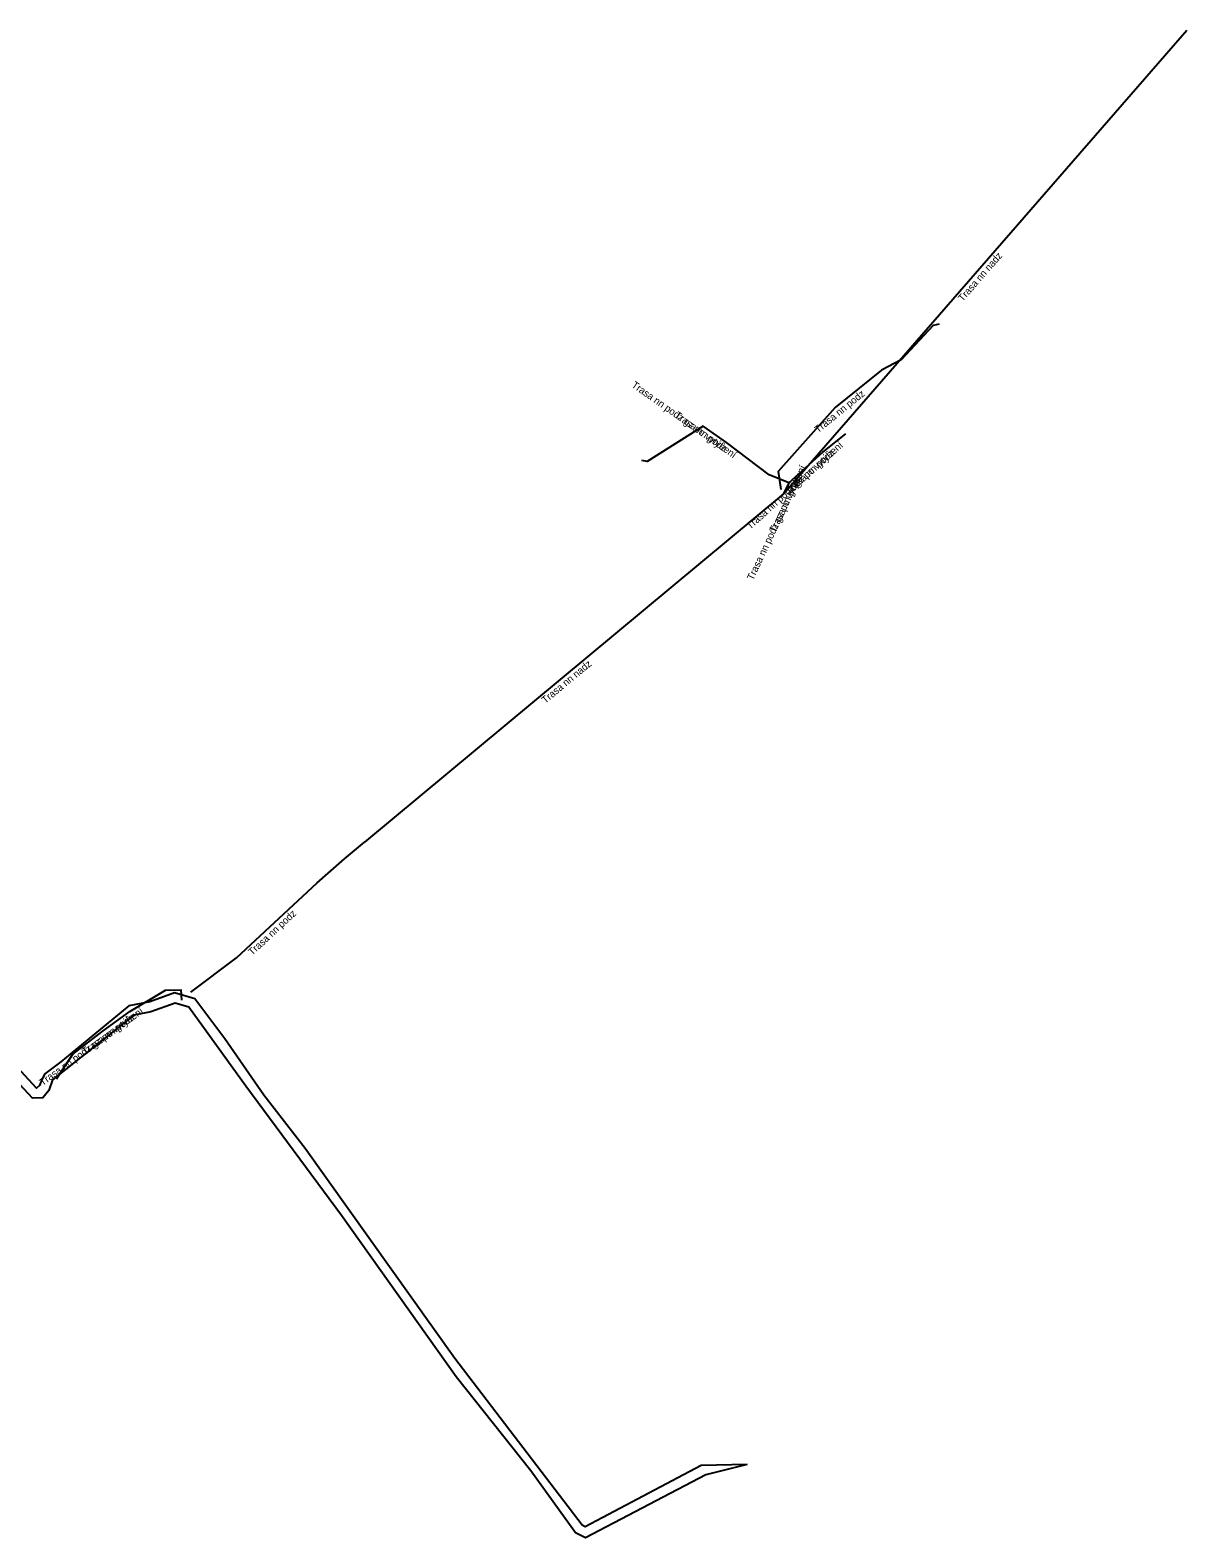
# Model space of a CAD drawing. Extents: x -703240 to -702678, y -1007635 to -1007322.
# Drawn here: x -702758.8 to -702677.9, y -1007438.8 to -1007333.3 of the extents above; entities that cross this region are included whole.
import ezdxf

# ---------------------------------------------------------------- set-up
doc = ezdxf.new("R2010")
doc.units = 0
for name, color, linetype in [('Popiskový text - Ostatní atributy Trasy', 7, 'Continuous'), ('Spojnice NN', 7, 'Continuous'), ('Spojnice VN', 7, 'Continuous')]:
    doc.layers.add(name, color=color, linetype=linetype)

msp = doc.modelspace()

# ---------------------------------------------------------------- linework, layer by layer
at = {"layer": 'Spojnice NN'}
for points in [[(-702706.1, -1007365.73), (-702677.88, -1007333.28)], [(-702695.21, -1007353.85), (-702695.62, -1007353.94), (-702697.88, -1007356.34), (-702699.25, -1007357.06), (-702702.48, -1007359.68), (-702706.47, -1007364.16), (-702706.3, -1007365.41)], [(-702705.74, -1007364.96), (-702707.1, -1007364.38), (-702710.1, -1007362.12), (-702711.72, -1007360.98), (-702715.63, -1007363.45), (-702716.02, -1007363.38)], [(-702705.74, -1007364.96), (-702707.1, -1007364.38), (-702710.1, -1007362.12), (-702711.72, -1007360.98), (-702715.63, -1007363.45), (-702716.02, -1007363.38)], [(-702705.74, -1007364.96), (-702703.34, -1007362.81), (-702701.74, -1007361.53)], [(-702705.74, -1007364.96), (-702703.34, -1007362.81), (-702701.74, -1007361.53)], [(-702705.74, -1007364.96), (-702706.1, -1007365.73)], [(-702705.74, -1007364.96), (-702706.1, -1007365.73)], [(-702706.1, -1007365.73), (-702735.43, -1007390.08)], [(-702747.56, -1007400.59), (-702744.37, -1007398.18), (-702738.74, -1007392.94), (-702736.82, -1007391.25), (-702735.43, -1007390.08)], [(-702756.97, -1007406.64), (-702755.83, -1007404.93), (-702753.7, -1007403.28), (-702751.84, -1007401.93), (-702749.35, -1007400.44), (-702748.27, -1007400.42), (-702748.23, -1007401.14)], [(-702756.97, -1007406.64), (-702755.83, -1007404.93), (-702753.7, -1007403.28), (-702751.84, -1007401.93), (-702749.35, -1007400.44), (-702748.27, -1007400.42), (-702748.23, -1007401.14)]]:
    msp.add_lwpolyline(points, dxfattribs=at)
at = {"layer": 'Spojnice VN'}
for points in [[(-702708.64, -1007433.64), (-702711.53, -1007434.36), (-702719.95, -1007438.76), (-702720.65, -1007438.42), (-702723.78, -1007434.07), (-702729, -1007427.49), (-702737.04, -1007416.21), (-702743.73, -1007407.16), (-702747.7, -1007401.63), (-702748.66, -1007401.36), (-702750.37, -1007401.96), (-702751.55, -1007402.2), (-702757.26, -1007406.72), (-702757.51, -1007407.47), (-702757.93, -1007407.98), (-702758.66, -1007408), (-702764.02, -1007402.25)], [(-702708.64, -1007433.64), (-702711.86, -1007433.7), (-702719.99, -1007437.99), (-702720.18, -1007437.88), (-702729.09, -1007426.21), (-702739.58, -1007411.53), (-702742.46, -1007407.78), (-702745.2, -1007403.86), (-702747.28, -1007401.04), (-702748.72, -1007400.64), (-702750.45, -1007401.27), (-702751.9, -1007401.55), (-702756.67, -1007405.45), (-702757.79, -1007406.29), (-702758, -1007406.69), (-702758.16, -1007407.11), (-702758.37, -1007407.3), (-702763.74, -1007401.49)]]:
    msp.add_lwpolyline(points, dxfattribs=at)

# ---------------------------------------------------------------- texts
at = {"layer": 'Popiskový text - Ostatní atributy Trasy'}
for s, rotation, p in [('Trasa nn nadz', 48.9883, (-702693.56, -1007352.31)), ('Trasa nn podz gz po vytýèení', 324.8658, (-702716.78, -1007358.21)), ('Trasa nn podz', 39.0471, (-702703.68, -1007361.49)), ('Trasa nn podz', 324.8658, (-702713.77, -1007360.33)), ('Trasa nn podz gz po vytýèení', 41.855, (-702708.43, -1007368.24)), ('Trasa nn podz', 41.855, (-702705.69, -1007365.79)), ('Trasa nn podz gz po vytýèení', 64.9424, (-702708.23, -1007371.81)), ('Trasa nn podz', 64.9424, (-702706.66, -1007368.47)), ('Trasa nn nadz', 39.6997, (-702722.77, -1007380.42)), ('Trasa nn podz', 42.9452, (-702743.28, -1007398.05)), ('Trasa nn podz gz po vytýèení', 35.9724, (-702757.94, -1007407.16)), ('Trasa nn podz', 35.9724, (-702754.95, -1007404.99))]:
    msp.add_text(s, height=0.5, rotation=rotation, dxfattribs=at).set_placement(p)

doc.saveas('drawing.dxf')
